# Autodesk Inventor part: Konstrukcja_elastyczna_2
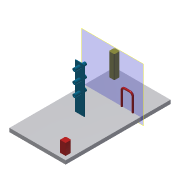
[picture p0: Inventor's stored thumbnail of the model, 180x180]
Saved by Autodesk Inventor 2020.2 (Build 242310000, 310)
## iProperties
Created: 2014-08
Part Number: Konstrukcja_elastyczna_2
Material: Ogólny
Document SubType Name: Modeling
Designer: F.Stasiak
Density: 1 g/cm^3
Appearance: Domyślna
Catalog Web Link: www.expertbooks.pl
Manager: www.cadconsulting.pl
Company: Fabian Stasiak CAD Consulting
Author: F.Stasiak
Subject: Zbiór ćwiczeń. Autodesk Inventor 2020. Kurs Professional
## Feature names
1. Wyciągnięcie proste1 [Extrusion]
2. Wyciągnięcie proste3 [Extrusion]
3. Wyciągnięcie proste9 [Extrusion]
4. Wyciągnięcie proste10 [Extrusion]
5. Wyciągnięcie proste11 [Extrusion]
6. Faza1 [Chamfer]
7. Przeciągnięcie2
8. Otwór5 [Hole]
9. Otwór6 [Hole]
## Parameters: d3 = 0, d15 = 0, d78 = 2 mm, d79 = 45 deg, d85 = 0, d91 = 0, d97 = 0, d98 = 45 mm, d100 = 118 deg, d101 = 90 deg, d102 = 2 mm, d103 = 4 mm, d104 = 53.5 mm, d105 = 18.631 mm, d106 = 45 mm, d108 = 118 deg, d109 = 90 deg, d110 = 2 mm, d111 = 4 mm, d112 = 53.5 mm, d113 = 18.631 mm, d126 = 0, d127 = 0
